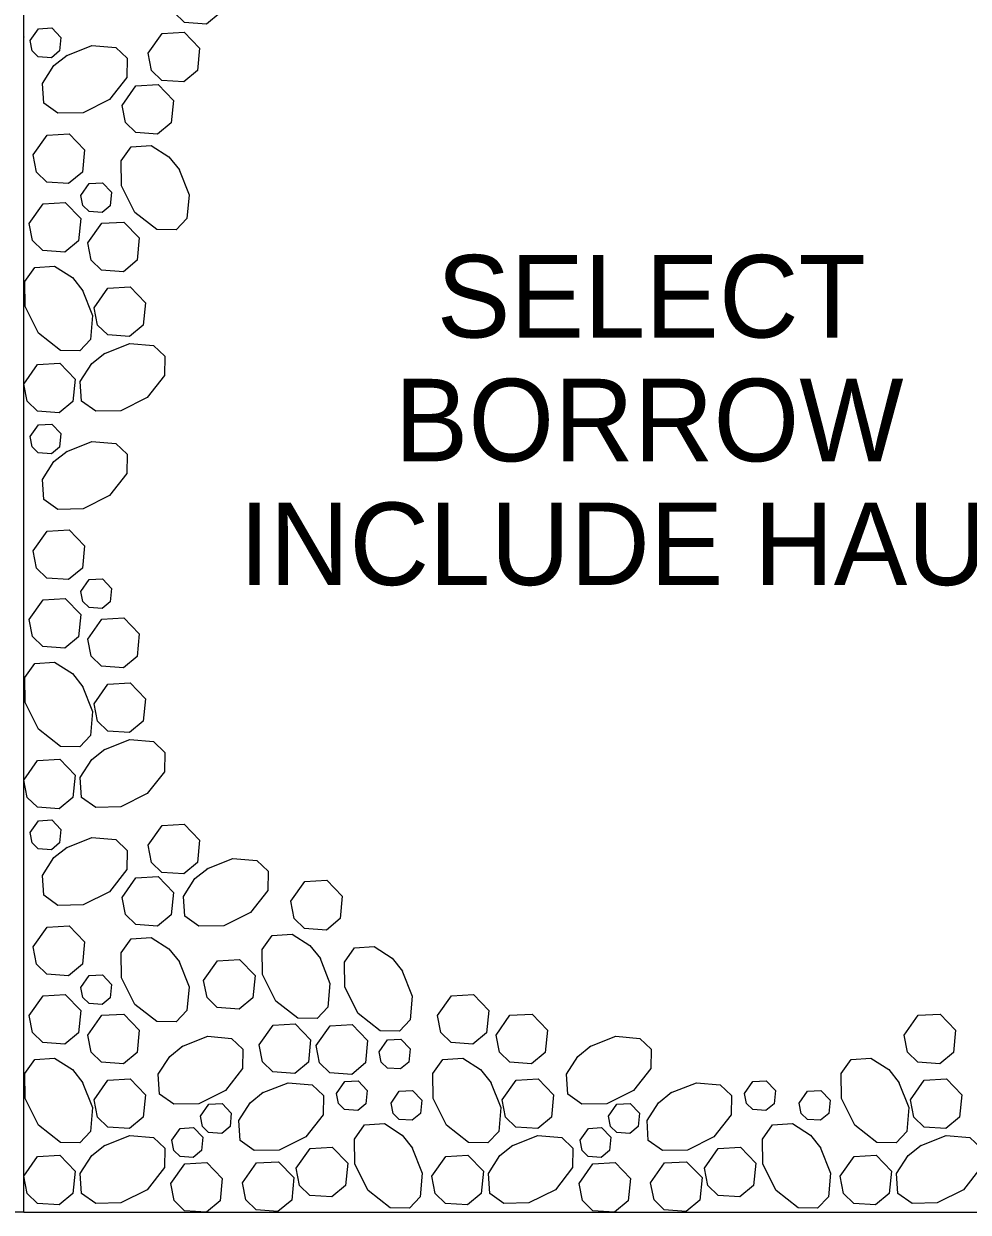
# Model space of a CAD drawing. Extents: x 99862 to 103151, y 100000 to 102076.
# Drawn here: x 100195.7 to 100378.8, y 100488.6 to 100719.1 of the extents above; entities that cross this region are included whole.
import ezdxf

# ---------------------------------------------------------------- set-up
doc = ezdxf.new("R2010")
doc.units = 0
for name, color, linetype in [('Level 2', 7, 'Continuous'), ('Level 20', 7, 'Continuous'), ('Level 45', 7, 'Continuous')]:
    doc.layers.add(name, color=color, linetype=linetype)

msp = doc.modelspace()

# ---------------------------------------------------------------- linework, layer by layer
at = {"layer": 'Level 2'}
for q in [(100195.7, 100818.64), (100067.7, 100488.64)]:
    msp.add_line((100195.7, 100488.64), q, dxfattribs=at)
at = {"layer": 'Level 45'}
msp.add_line((100195.7, 100488.64), (100442.38, 100488.64), dxfattribs=at)
for points in [[(100224.24, 100724.59), (100226.93, 100728.42), (100231.22, 100728.66), (100234.2, 100725.57), (100233.77, 100721.23), (100231.12, 100719.02), (100226.88, 100719.33), (100224.89, 100721.27), (100224.24, 100724.59)], [(100195.7, 100716.54), (100195.7, 100716.54), (100195.7, 100716.52)], [(100196.93, 100715.85), (100198.54, 100718.14), (100201.12, 100718.29), (100202.91, 100716.43), (100202.65, 100713.83), (100201.06, 100712.51), (100198.51, 100712.69), (100197.32, 100713.85), (100196.93, 100715.85)], [(100219.83, 100713.39), (100222.51, 100717.22), (100226.81, 100717.46), (100229.79, 100714.37), (100229.36, 100710.03), (100226.71, 100707.82), (100222.47, 100708.13), (100220.48, 100710.07), (100219.83, 100713.39)], [(100203.89, 100712.9), (100208.92, 100714.89), (100213.55, 100714.5), (100215.74, 100712.41), (100215.67, 100708.66), (100212.34, 100704.4), (100207.19, 100701.82), (100202.33, 100701.74), (100199.6, 100703.68), (100199.34, 100707.54), (100201.56, 100711), (100204.1, 100713.03)], [(100214.77, 100703.27), (100217.45, 100707.1), (100221.75, 100707.34), (100224.73, 100704.25), (100224.3, 100699.91), (100221.65, 100697.7), (100217.41, 100698.01), (100215.41, 100699.95), (100214.77, 100703.27)], [(100197.52, 100693.67), (100200.21, 100697.5), (100204.5, 100697.74), (100207.49, 100694.65), (100207.06, 100690.31), (100204.4, 100688.11), (100200.16, 100688.41), (100198.17, 100690.35), (100197.52, 100693.67)], [(100225.75, 100690.97), (100227.74, 100685.94), (100227.35, 100681.32), (100225.26, 100679.12), (100221.51, 100679.19), (100217.25, 100682.53), (100214.67, 100687.68), (100214.59, 100692.53), (100216.53, 100695.27), (100220.39, 100695.52), (100223.85, 100693.31), (100225.88, 100690.77)], [(100206.76, 100685.83), (100208.37, 100688.13), (100210.95, 100688.28), (100212.74, 100686.42), (100212.48, 100683.82), (100210.89, 100682.49), (100208.35, 100682.68), (100207.15, 100683.84), (100206.76, 100685.83)], [(100196.77, 100680.39), (100199.46, 100684.21), (100203.75, 100684.46), (100206.74, 100681.36), (100206.3, 100677.03), (100203.65, 100674.82), (100199.41, 100675.13), (100197.42, 100677.06), (100196.77, 100680.39)], [(100208.13, 100676.59), (100210.82, 100680.42), (100215.11, 100680.66), (100218.1, 100677.57), (100217.67, 100673.23), (100215.01, 100671.02), (100210.77, 100671.33), (100208.78, 100673.27), (100208.13, 100676.59)], [(100207.04, 100667.55), (100209.04, 100662.52), (100208.64, 100657.89), (100206.55, 100655.7), (100202.8, 100655.77), (100198.54, 100659.1), (100195.96, 100664.25), (100195.88, 100669.11), (100197.82, 100671.84), (100201.69, 100672.1), (100205.15, 100669.88), (100207.17, 100667.34)], [(100209.33, 100664.01), (100212.02, 100667.83), (100216.31, 100668.08), (100219.29, 100664.98), (100218.86, 100660.64), (100216.21, 100658.44), (100211.97, 100658.75), (100209.98, 100660.68), (100209.33, 100664)], [(100211.21, 100655.11), (100216.24, 100657.11), (100220.86, 100656.71), (100223.06, 100654.62), (100222.99, 100650.87), (100219.65, 100646.61), (100214.5, 100644.03), (100209.65, 100643.95), (100206.91, 100645.89), (100206.65, 100649.75), (100208.87, 100653.21), (100211.41, 100655.24)], [(100195.7, 100649.21), (100198.39, 100653.04), (100202.68, 100653.28), (100205.67, 100650.19), (100205.24, 100645.85), (100202.58, 100643.65), (100198.34, 100643.95), (100196.35, 100645.89), (100195.7, 100649.21)], [(100196.93, 100639.05), (100198.54, 100641.35), (100201.12, 100641.49), (100202.91, 100639.64), (100202.65, 100637.03), (100201.06, 100635.71), (100198.51, 100635.89), (100197.32, 100637.05), (100196.93, 100639.05)], [(100195.7, 100639.74), (100195.7, 100639.74), (100195.7, 100639.72)], [(100203.89, 100636.1), (100208.92, 100638.1), (100213.55, 100637.7), (100215.74, 100635.61), (100215.67, 100631.86), (100212.34, 100627.6), (100207.19, 100625.02), (100202.33, 100624.94), (100199.6, 100626.88), (100199.34, 100630.75), (100201.56, 100634.21), (100204.1, 100636.23)], [(100197.52, 100616.88), (100200.21, 100620.7), (100204.5, 100620.95), (100207.49, 100617.85), (100207.06, 100613.52), (100204.4, 100611.31), (100200.16, 100611.62), (100198.17, 100613.55), (100197.52, 100616.88)], [(100206.76, 100609.04), (100208.37, 100611.33), (100210.95, 100611.48), (100212.74, 100609.62), (100212.48, 100607.02), (100210.89, 100605.7), (100208.35, 100605.88), (100207.15, 100607.04), (100206.76, 100609.04)], [(100196.77, 100603.59), (100199.46, 100607.42), (100203.75, 100607.66), (100206.74, 100604.57), (100206.3, 100600.23), (100203.65, 100598.03), (100199.41, 100598.33), (100197.42, 100600.27), (100196.77, 100603.59)], [(100208.13, 100599.79), (100210.82, 100603.62), (100215.11, 100603.87), (100218.1, 100600.77), (100217.67, 100596.43), (100215.01, 100594.23), (100210.77, 100594.54), (100208.78, 100596.47), (100208.13, 100599.79)], [(100207.04, 100590.75), (100209.04, 100585.72), (100208.64, 100581.1), (100206.55, 100578.9), (100202.8, 100578.97), (100198.54, 100582.3), (100195.96, 100587.46), (100195.88, 100592.31), (100197.82, 100595.04), (100201.69, 100595.3), (100205.15, 100593.09), (100207.17, 100590.55)], [(100209.33, 100587.21), (100212.02, 100591.03), (100216.31, 100591.28), (100219.29, 100588.19), (100218.86, 100583.85), (100216.21, 100581.64), (100211.97, 100581.95), (100209.98, 100583.88), (100209.33, 100587.21)], [(100211.21, 100578.32), (100216.24, 100580.31), (100220.86, 100579.91), (100223.06, 100577.82), (100222.99, 100574.07), (100219.65, 100569.81), (100214.5, 100567.23), (100209.65, 100567.15), (100206.91, 100569.09), (100206.65, 100572.96), (100208.87, 100576.42), (100211.41, 100578.44)], [(100195.7, 100572.42), (100198.39, 100576.24), (100202.68, 100576.49), (100205.67, 100573.39), (100205.24, 100569.06), (100202.58, 100566.85), (100198.34, 100567.16), (100196.35, 100569.09), (100195.7, 100572.42)], [(100196.93, 100562.25), (100198.54, 100564.55), (100201.12, 100564.7), (100202.91, 100562.84), (100202.65, 100560.24), (100201.06, 100558.91), (100198.51, 100559.1), (100197.32, 100560.26), (100196.93, 100562.25)], [(100195.7, 100562.95), (100195.7, 100562.94), (100195.7, 100562.92)], [(100219.83, 100559.8), (100222.51, 100563.62), (100226.81, 100563.87), (100229.79, 100560.77), (100229.36, 100556.44), (100226.71, 100554.23), (100222.47, 100554.54), (100220.48, 100556.47), (100219.83, 100559.8)], [(100203.89, 100559.31), (100208.92, 100561.3), (100213.55, 100560.9), (100215.74, 100558.81), (100215.67, 100555.07), (100212.34, 100550.8), (100207.19, 100548.23), (100202.33, 100548.14), (100199.6, 100550.09), (100199.34, 100553.95), (100201.56, 100557.41), (100204.1, 100559.44)], [(100231.22, 100555.24), (100236.25, 100557.24), (100240.87, 100556.84), (100243.07, 100554.75), (100243, 100551), (100239.67, 100546.74), (100234.52, 100544.16), (100229.66, 100544.08), (100226.93, 100546.02), (100226.67, 100549.89), (100228.89, 100553.34), (100231.43, 100555.37)], [(100214.77, 100549.68), (100217.45, 100553.5), (100221.75, 100553.75), (100224.73, 100550.65), (100224.3, 100546.32), (100221.65, 100544.11), (100217.41, 100544.42), (100215.41, 100546.35), (100214.77, 100549.68)], [(100247.48, 100548.93), (100250.17, 100552.75), (100254.47, 100553), (100257.45, 100549.9), (100257.02, 100545.57), (100254.37, 100543.36), (100250.13, 100543.67), (100248.13, 100545.6), (100247.49, 100548.93)], [(100197.52, 100540.08), (100200.21, 100543.91), (100204.5, 100544.15), (100207.49, 100541.06), (100207.06, 100536.72), (100204.4, 100534.51), (100200.16, 100534.82), (100198.17, 100536.75), (100197.52, 100540.08)], [(100225.75, 100537.38), (100227.74, 100532.35), (100227.35, 100527.73), (100225.26, 100525.53), (100221.51, 100525.6), (100217.25, 100528.93), (100214.67, 100534.09), (100214.59, 100538.94), (100216.53, 100541.67), (100220.39, 100541.93), (100223.85, 100539.72), (100225.88, 100537.18)], [(100253.08, 100538.03), (100255.08, 100533), (100254.68, 100528.38), (100252.59, 100526.18), (100248.84, 100526.25), (100244.58, 100529.59), (100242, 100534.74), (100241.92, 100539.59), (100243.86, 100542.33), (100247.72, 100542.58), (100251.18, 100540.37), (100253.21, 100537.83)], [(100269.02, 100535.59), (100271.02, 100530.56), (100270.62, 100525.94), (100268.53, 100523.74), (100264.78, 100523.81), (100260.52, 100527.15), (100257.94, 100532.3), (100257.86, 100537.15), (100259.8, 100539.88), (100263.67, 100540.14), (100267.13, 100537.93), (100269.15, 100535.39)], [(100230.58, 100533.57), (100233.27, 100537.4), (100237.56, 100537.64), (100240.55, 100534.55), (100240.12, 100530.21), (100237.46, 100528.01), (100233.22, 100528.31), (100231.23, 100530.25), (100230.58, 100533.57)], [(100206.76, 100532.24), (100208.37, 100534.54), (100210.95, 100534.68), (100212.74, 100532.83), (100212.48, 100530.23), (100210.89, 100528.9), (100208.35, 100529.09), (100207.15, 100530.25), (100206.76, 100532.24)], [(100196.77, 100526.8), (100199.46, 100530.62), (100203.75, 100530.87), (100206.74, 100527.77), (100206.3, 100523.44), (100203.65, 100521.23), (100199.41, 100521.54), (100197.42, 100523.47), (100196.77, 100526.8)], [(100275.92, 100526.8), (100278.61, 100530.62), (100282.9, 100530.87), (100285.88, 100527.77), (100285.45, 100523.44), (100282.8, 100521.23), (100278.56, 100521.54), (100276.57, 100523.47), (100275.92, 100526.8)], [(100208.13, 100523), (100210.82, 100526.82), (100215.11, 100527.07), (100218.1, 100523.97), (100217.67, 100519.64), (100215.01, 100517.43), (100210.77, 100517.74), (100208.78, 100519.67), (100208.13, 100523)], [(100241.34, 100521.1), (100244.03, 100524.93), (100248.33, 100525.17), (100251.31, 100522.08), (100250.88, 100517.74), (100248.23, 100515.54), (100243.99, 100515.84), (100241.99, 100517.78), (100241.35, 100521.1)], [(100252.4, 100520.94), (100255.09, 100524.77), (100259.39, 100525.01), (100262.37, 100521.92), (100261.94, 100517.58), (100259.29, 100515.37), (100255.05, 100515.68), (100253.05, 100517.62), (100252.41, 100520.94)], [(100287.28, 100523), (100289.97, 100526.82), (100294.26, 100527.07), (100297.25, 100523.97), (100296.81, 100519.64), (100294.16, 100517.43), (100289.92, 100517.74), (100287.93, 100519.67), (100287.28, 100523)], [(100366.43, 100523), (100369.12, 100526.82), (100373.41, 100527.07), (100376.4, 100523.97), (100375.96, 100519.64), (100373.31, 100517.43), (100369.07, 100517.74), (100367.08, 100519.67), (100366.43, 100523)], [(100226.34, 100520.75), (100231.37, 100522.75), (100235.99, 100522.35), (100238.19, 100520.26), (100238.12, 100516.51), (100234.79, 100512.25), (100229.64, 100509.67), (100224.78, 100509.59), (100222.05, 100511.53), (100221.79, 100515.4), (100224.01, 100518.86), (100226.55, 100520.88)], [(100305.49, 100520.75), (100310.52, 100522.75), (100315.14, 100522.35), (100317.34, 100520.26), (100317.27, 100516.51), (100313.94, 100512.25), (100308.78, 100509.67), (100303.93, 100509.59), (100301.2, 100511.53), (100300.94, 100515.4), (100303.15, 100518.86), (100305.69, 100520.88)], [(100264.64, 100519.76), (100266.25, 100522.05), (100268.83, 100522.2), (100270.62, 100520.34), (100270.36, 100517.74), (100268.77, 100516.42), (100266.23, 100516.6), (100265.03, 100517.76), (100264.64, 100519.76)], [(100207.04, 100513.95), (100209.04, 100508.92), (100208.64, 100504.3), (100206.55, 100502.1), (100202.8, 100502.18), (100198.54, 100505.51), (100195.96, 100510.66), (100195.88, 100515.52), (100197.82, 100518.25), (100201.69, 100518.51), (100205.15, 100516.29), (100207.17, 100513.75)], [(100286.19, 100513.95), (100288.19, 100508.92), (100287.79, 100504.3), (100285.7, 100502.1), (100281.95, 100502.18), (100277.69, 100505.51), (100275.11, 100510.66), (100275.03, 100515.52), (100276.97, 100518.25), (100280.83, 100518.51), (100284.29, 100516.29), (100286.32, 100513.75)], [(100365.34, 100513.95), (100367.33, 100508.92), (100366.93, 100504.3), (100364.85, 100502.1), (100361.1, 100502.18), (100356.84, 100505.51), (100354.26, 100510.66), (100354.17, 100515.52), (100356.12, 100518.25), (100359.98, 100518.51), (100363.44, 100516.29), (100365.47, 100513.75)], [(100209.33, 100510.41), (100212.02, 100514.24), (100216.31, 100514.48), (100219.29, 100511.39), (100218.86, 100507.05), (100216.21, 100504.85), (100211.97, 100505.15), (100209.98, 100507.09), (100209.33, 100510.41)], [(100241.95, 100511.77), (100246.98, 100513.76), (100251.6, 100513.36), (100253.8, 100511.27), (100253.73, 100507.52), (100250.4, 100503.26), (100245.24, 100500.69), (100240.39, 100500.6), (100237.66, 100502.54), (100237.4, 100506.41), (100239.61, 100509.87), (100242.15, 100511.9)], [(100256.32, 100511.69), (100257.93, 100513.98), (100260.51, 100514.13), (100262.3, 100512.27), (100262.04, 100509.67), (100260.45, 100508.35), (100257.9, 100508.53), (100256.71, 100509.69), (100256.32, 100511.69)], [(100288.48, 100510.41), (100291.17, 100514.24), (100295.46, 100514.48), (100298.44, 100511.39), (100298.01, 100507.05), (100295.36, 100504.85), (100291.12, 100505.15), (100289.13, 100507.09), (100288.48, 100510.41)], [(100321.1, 100511.77), (100326.13, 100513.76), (100330.75, 100513.36), (100332.95, 100511.27), (100332.88, 100507.52), (100329.54, 100503.26), (100324.39, 100500.69), (100319.54, 100500.6), (100316.8, 100502.54), (100316.55, 100506.41), (100318.76, 100509.87), (100321.3, 100511.9)], [(100335.47, 100511.69), (100337.08, 100513.98), (100339.66, 100514.13), (100341.45, 100512.27), (100341.19, 100509.67), (100339.6, 100508.35), (100337.05, 100508.53), (100335.86, 100509.69), (100335.47, 100511.69)], [(100367.62, 100510.41), (100370.31, 100514.24), (100374.61, 100514.48), (100377.59, 100511.39), (100377.16, 100507.05), (100374.51, 100504.85), (100370.27, 100505.15), (100368.27, 100507.09), (100367.63, 100510.41)], [(100266.91, 100509.8), (100268.52, 100512.09), (100271.1, 100512.24), (100272.89, 100510.38), (100272.63, 100507.78), (100271.04, 100506.46), (100268.5, 100506.64), (100267.3, 100507.8), (100266.91, 100509.8)], [(100346.06, 100509.8), (100347.67, 100512.09), (100350.25, 100512.24), (100352.04, 100510.38), (100351.78, 100507.78), (100350.19, 100506.46), (100347.64, 100506.64), (100346.45, 100507.8), (100346.06, 100509.8)], [(100229.96, 100507.28), (100231.58, 100509.57), (100234.15, 100509.72), (100235.94, 100507.86), (100235.69, 100505.26), (100234.09, 100503.93), (100231.55, 100504.12), (100230.35, 100505.28), (100229.96, 100507.27)], [(100309.11, 100507.28), (100310.73, 100509.57), (100313.3, 100509.72), (100315.09, 100507.86), (100314.83, 100505.26), (100313.24, 100503.93), (100310.7, 100504.12), (100309.5, 100505.28), (100309.11, 100507.27)], [(100224.41, 100502.61), (100226.03, 100504.9), (100228.6, 100505.05), (100230.4, 100503.19), (100230.14, 100500.59), (100228.55, 100499.27), (100226, 100499.45), (100224.8, 100500.61), (100224.42, 100502.61)], [(100270.97, 100501.26), (100272.97, 100496.23), (100272.57, 100491.61), (100270.48, 100489.42), (100266.73, 100489.49), (100262.47, 100492.82), (100259.9, 100497.97), (100259.81, 100502.83), (100261.75, 100505.56), (100265.62, 100505.82), (100269.08, 100503.6), (100271.1, 100501.06)], [(100303.56, 100502.61), (100305.18, 100504.9), (100307.75, 100505.05), (100309.54, 100503.19), (100309.29, 100500.59), (100307.69, 100499.27), (100305.15, 100499.45), (100303.95, 100500.61), (100303.56, 100502.61)], [(100350.12, 100501.26), (100352.12, 100496.23), (100351.72, 100491.61), (100349.63, 100489.42), (100345.88, 100489.49), (100341.62, 100492.82), (100339.04, 100497.97), (100338.96, 100502.83), (100340.9, 100505.56), (100344.77, 100505.82), (100348.23, 100503.6), (100350.25, 100501.06)], [(100211.21, 100501.52), (100216.24, 100503.51), (100220.86, 100503.11), (100223.06, 100501.03), (100222.99, 100497.28), (100219.65, 100493.01), (100214.5, 100490.44), (100209.65, 100490.35), (100206.91, 100492.3), (100206.65, 100496.16), (100208.87, 100499.62), (100211.41, 100501.65)], [(100290.36, 100501.52), (100295.39, 100503.51), (100300.01, 100503.11), (100302.2, 100501.03), (100302.13, 100497.28), (100298.8, 100493.01), (100293.65, 100490.44), (100288.79, 100490.35), (100286.06, 100492.3), (100285.8, 100496.16), (100288.02, 100499.62), (100290.56, 100501.65)], [(100369.5, 100501.52), (100374.54, 100503.51), (100379.16, 100503.11), (100381.35, 100501.03), (100381.28, 100497.28), (100377.95, 100493.01), (100372.8, 100490.44), (100367.94, 100490.35), (100365.21, 100492.3), (100364.95, 100496.16), (100367.17, 100499.62), (100369.71, 100501.65)], [(100195.7, 100495.62), (100198.39, 100499.45), (100202.68, 100499.69), (100205.67, 100496.6), (100205.24, 100492.26), (100202.58, 100490.05), (100198.34, 100490.36), (100196.35, 100492.3), (100195.7, 100495.62)], [(100248.54, 100497.17), (100251.23, 100500.99), (100255.52, 100501.24), (100258.51, 100498.14), (100258.07, 100493.81), (100255.42, 100491.6), (100251.18, 100491.91), (100249.19, 100493.84), (100248.54, 100497.17)], [(100274.85, 100495.62), (100277.54, 100499.45), (100281.83, 100499.69), (100284.82, 100496.6), (100284.38, 100492.26), (100281.73, 100490.05), (100277.49, 100490.36), (100275.5, 100492.3), (100274.85, 100495.62)], [(100327.69, 100497.17), (100330.38, 100500.99), (100334.67, 100501.24), (100337.65, 100498.14), (100337.22, 100493.81), (100334.57, 100491.6), (100330.33, 100491.91), (100328.34, 100493.84), (100327.69, 100497.17)], [(100354, 100495.62), (100356.69, 100499.45), (100360.98, 100499.69), (100363.96, 100496.6), (100363.53, 100492.26), (100360.88, 100490.05), (100356.64, 100490.36), (100354.65, 100492.3), (100354, 100495.62)], [(100224.24, 100494.2), (100226.93, 100498.03), (100231.22, 100498.27), (100234.2, 100495.18), (100233.77, 100490.84), (100231.12, 100488.64)], [(100238.11, 100494.36), (100240.8, 100498.19), (100245.09, 100498.43), (100248.08, 100495.34), (100247.65, 100491), (100244.99, 100488.79), (100240.75, 100489.1), (100238.76, 100491.04), (100238.11, 100494.36)], [(100303.38, 100494.2), (100306.07, 100498.03), (100310.37, 100498.27), (100313.35, 100495.18), (100312.92, 100490.84), (100310.27, 100488.64)], [(100317.26, 100494.36), (100319.95, 100498.19), (100324.24, 100498.43), (100327.23, 100495.34), (100326.79, 100491), (100324.14, 100488.79), (100319.9, 100489.1), (100317.91, 100491.04), (100317.26, 100494.36)], [(100231.11, 100488.64), (100226.88, 100488.94), (100224.89, 100490.88), (100224.24, 100494.2)], [(100310.26, 100488.64), (100306.03, 100488.94), (100304.03, 100490.88), (100303.39, 100494.2)]]:
    msp.add_lwpolyline(points, dxfattribs=at)

# ---------------------------------------------------------------- texts
at = {"layer": 'Level 20'}
for s, p in [('SELECT', (100275.78, 100658.26)), ('BORROW', (100267.63, 100634.26)), ('INCLUDE HAUL', (100237.45, 100610.26))]:
    msp.add_text(s, height=16, dxfattribs=at).set_placement(p)

doc.saveas('drawing.dxf')
